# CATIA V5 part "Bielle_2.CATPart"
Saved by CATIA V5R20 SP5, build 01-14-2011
Part number: Bielle_2
Publications: "Droite.1", "Droite.2", "Droite.3"
Bounding box of the stored display mesh (mm): x -200 to 0, y 0 to 300, z -320 to -74
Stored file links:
  J:\Thinkmotion\Projet IAO\A envoyer\Bielle_2.CATPart
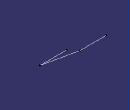
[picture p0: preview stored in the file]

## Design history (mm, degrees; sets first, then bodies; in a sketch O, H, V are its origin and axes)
Set1
  Line1: type PtPt, FirstPoint Point7, SecondPoint Point8
  Point1 "B": stored without definition
  Point2 "C": stored without definition
  Line2: type Normal, RefPoint Point5, RefSkin yz-plane, Start 0, End -200
  Point3 "B": stored without definition
  Line3: type Normal, RefPoint Point6, RefSkin yz-plane, Start 0, End -200
  Point4 "C": stored without definition
  Point5 "B": stored without definition
  Point6 "C": stored without definition
  Point7 "B": stored without definition
  Point8 "C": stored without definition
Body1 (main body)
